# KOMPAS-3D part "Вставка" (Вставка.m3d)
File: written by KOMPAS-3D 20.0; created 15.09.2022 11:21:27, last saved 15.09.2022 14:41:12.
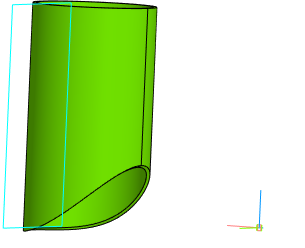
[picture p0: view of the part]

Document properties: Полное имя файла: D:\YAKOVLEV\ПРОЕКТЫ\ДЦ-2. ДП-7 Газопровод Окожушивание\ПРОБА Соединение труб. Окожушивание\Вставка.m3d

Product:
- Part/product: Вставка
    Материал: Сталь 45  ГОСТ 1050-2013 (density 7810 kg/m3)
    Масса: 1309.6

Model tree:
1. Эскиз:1  (with: Смещенная плоскость:1)
2. Обечайка:1
     Расстояние 1 = 1647; Толщина листового тела = 30; Радиус сгиба = 500; Коэффициент = 0.4; Величина сгиба = 10; Зазор = 0.01
3. Касательная плоскость:1  (with: Обечайка:1)
4. Фаска:1  (with: Обечайка:1)
     Угол = 45; Длина 1 = 28; Длина 2 = 28
5. Развертка  (labels: Сталь 45  ГОСТ 1050-2013)

Expressions: 900+100
Referenced files in D:\YAKOVLEV\ПРОЕКТЫ\ДЦ-2. ДП-7 Газопровод Окожушивание\ПРОБА Соединение труб. Окожушивание\: Соединение труб.a3d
